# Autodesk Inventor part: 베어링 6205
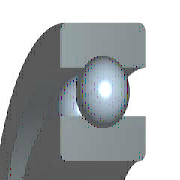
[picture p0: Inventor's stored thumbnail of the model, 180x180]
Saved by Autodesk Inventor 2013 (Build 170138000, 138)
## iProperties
IsCustomPart: 1
Created: 2009-02
Part Number: 베어링 6205
Material: 강, 연강
Description: 깊은 그루브 볼 베어링
Document SubType Name: Modeling
Standard: KS B 2023
Designer: 진현석
Standards Organization: KS
Language: ko-KR
Size Designation: 6205 - 25 x 52 x 15
Categories: <MemberInstance><Categories><Category DisplayName="샤프트 부품" InternalName="7f7aeb1f-a693-4053-b835-cee3144e0d98" Mnemonic="SHFT"><Category DisplayName="베어링" Inter
Density: 1 g/cm^3
Author: 진현석
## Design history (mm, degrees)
sketch "스케치" dims "d0" = 7.02 (= -0.26 x WD + 0.26 x BD)
  geometry: L1 (3.99, 19.25)-(11.01, 19.25); L2 (7.5, 19.25)-(7.5, 15.74); L3 (7.5, 19.25)-(7.5, 22.76); L4 (4.892, 16.901)-(0, 16.901); L5 (0, 12.5)-(15, 12.5); L6 (4.892, 21.599)-(0, 21.599); L7 (0, 26)-(15, 26); L8 (15, 12.5)-(15, 16.901); L9 (10.108, 16.901)-(15, 16.901); L10 (10.108, 21.599)-(15, 21.599); L11 (15, 26)-(15, 21.599); L12 (-1.4, 0)-(8.4, 0) reference; L13 (0, -0.3)-(0, 5.3) reference
  constraints: 22 end point, 4 point on line, 2 collinear, 2 perpendicular, 2 symmetric about line, 1 midpoint, 1 parallel, 14 other
  dimensions: "d9" = 25 diameter of L5 L12 (= WD); "d11" = 52 diameter of L7 L12 (= BD); "d12" = 15 distance between parallel lines of L8 L13 (= KB); "d13" = 33.802 diameter of L9 L12 (= 0.326 x BD + 0.674 x WD)
revolve "본체" stored, may be unused: angle "d6" = 90 deg
revolve "볼" stored, may be unused: angle "d7" = 90 deg
pattern_circular "IDS_ARRAYBALL[SIMPL:T]" dims angle "d3" = 360 deg
body "Solid1"
fillet "모깎기1" dims "d1" = 1 (= KRS)
other parameters: "WD" = 25 [user parameter; used in 5 equation terms], "BD" = 52 [user parameter; used in 5 equation terms], "KB" = 15 [user parameter; used in 1 equation term], "KRS" = 1 [user parameter; used in 1 equation term], "d4" = 0, "d5" = 0, "d8" = 0, "d14" = 0, "d15" = 0, "BBA" = 0 [user parameter], "BC0" = 7800000 [user parameter], "BC" = 1.4e+07 [user parameter], "BR" = 26 (= 0.5 x BD) [user parameter], "WR" = 12.5 (= 0.5 x WD) [user parameter]
